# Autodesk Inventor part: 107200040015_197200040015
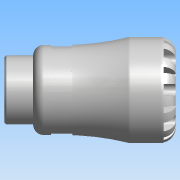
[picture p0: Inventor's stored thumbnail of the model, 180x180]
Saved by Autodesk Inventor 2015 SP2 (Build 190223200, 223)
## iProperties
Created: 2016-12
Part Number: 107200040015_197200040015
Material: PVC-Piping
Description: PLASSON MALE INTEGRAL BRASS THREAD 40X1.1/2" SERIES 1
Document SubType Name: Modeling
Designer: KIM
Mass: 61.7504 g
Surface Area: 140.097 cm^2
Volume: 44.1074 cm^3
Density: 1.4 g/cm^3
Appearance: Smooth - White
Author: KIM
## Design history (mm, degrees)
derived "1072.ipt"
feature "Solid1::1072.ipt"
tag "TaggingFeature1"
body "Solid1"
other parameters: "d0" = 113, "d1" = 30.66, "d6" = 73, "d8" = 59.5, "d13" = 8, "d14" = 8, "d15" = 0, "d17" = 360 deg, "d19" = 8 deg, "d20" = 0.8, "d21" = 0.8, "d22" = 8 deg, "d24" = 0, "d26" = 360 deg, "d32" = 7, "d33" = 7, "d34" = 45.485, "d38" = 19, "d39" = 1.36455, "d42" = 14, "d43" = 9.2, "d45" = 15.68, "d46" = 0, "d59" = 360 deg, "d61" = 11.9, "d62" = 0.8, "d64" = 0, "d65" = 0.7, "d68" = 5.71429, "H_" = 113, "l_" = 73, "R_" = 45.485, "l_2" = 19, "d9" = 10
